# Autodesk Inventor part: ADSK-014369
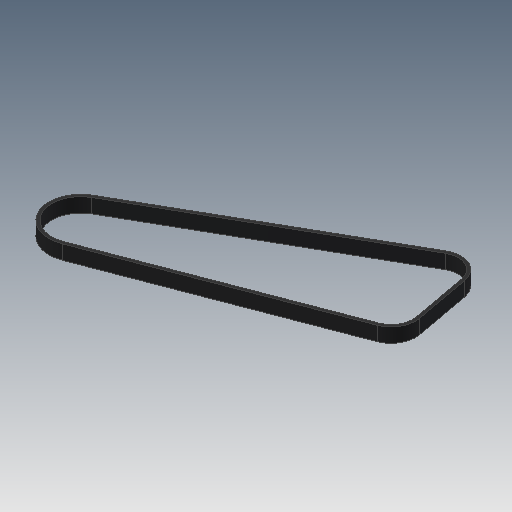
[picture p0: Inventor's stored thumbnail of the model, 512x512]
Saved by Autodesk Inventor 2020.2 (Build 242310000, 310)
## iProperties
Created: 2019-10
Part Number: ADSK-014369
Material: Gummi
Document SubType Name: Modeling
Designer: lutzd
Mass: 255.728 g
Surface Area: 1099.91 cm^2
Volume: 274.977 cm^3
Density: 0.93 g/cm^3
Appearance: Gummi - Schwarz
VLDS_Profile: Default Part
VLDS_TimeStamp: 2016-07-29
VLDS_FailCnt: 0
VLDS_AcceptCnt: 0
Dimensions: 402,8x30x604,5 mm
Mass: 0,256 kg
DocNumber: ADSK-014369
Folder: 01 - Themengebiete\Simplification\01 - Packaging machine\Parts\
VDS_Category: 3D Komponenten
VDS_NumSchm: Autodesk
VLT_Material: Gummi
Title: belt
Author: lutzd
Revision Number: -
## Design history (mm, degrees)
feature "Fläche1"
feature "Fläche2"
feature "Fläche3"
sketch "Skizze1"
  geometry: L1 (42.579, 7.84)-(64.256, -109.894); L2 (-21.455, 37.604)-(-496.729, -233.56); L3 (-444.754, -343.535)-(36.042, -160.086); L4 (-499.702, -228.348)-(-24.428, 42.816); L5 (48.479, 8.926)-(70.157, -108.808); L6 (38.181, -165.692)-(-442.616, -349.141); A1 r 43.294 centre (0, 0) between (42.579, 7.84) and (-21.455, 37.604) reference; A2 r 45 centre (20, -118.043) between (64.256, -109.894) and (36.042, -160.086) reference; A3 r 61 centre (-466.5, -286.543) between (-496.729, -233.56) and (-444.754, -343.535) reference; A4 r 43.294 centre (0, 0) between (42.579, 7.84) and (-21.455, 37.604); A5 r 45 centre (20, -118.043) between (36.042, -160.086) and (64.256, -109.894); A6 r 61 centre (-466.5, -286.543) between (-496.729, -233.56) and (-444.754, -343.535); A7 r 49.294 centre (0, 0) between (48.479, 8.926) and (-24.428, 42.816); A8 r 51 centre (20, -118.043) between (38.181, -165.692) and (70.157, -108.808); A9 r 67 centre (-466.5, -286.543) between (-499.702, -228.348) and (-442.616, -349.141); 1 further point
  constraints: 18 point on circle, 12 end point, 11 tangent, 6 centre point, 1 concentric, 5 other
  dimensions: "d0" = 6 distance between parallel lines of L2 L4
extrude "Extrusion1" new body sketch "Skizze1" stored distance "d1" = 30; taper "d2" = 0 deg
node "Volumenkörper1"
node "Flä1"
node "Flä2"
node "Flä3"
